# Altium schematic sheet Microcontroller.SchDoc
size A; SheetNumber: 3; SheetTotal: 5
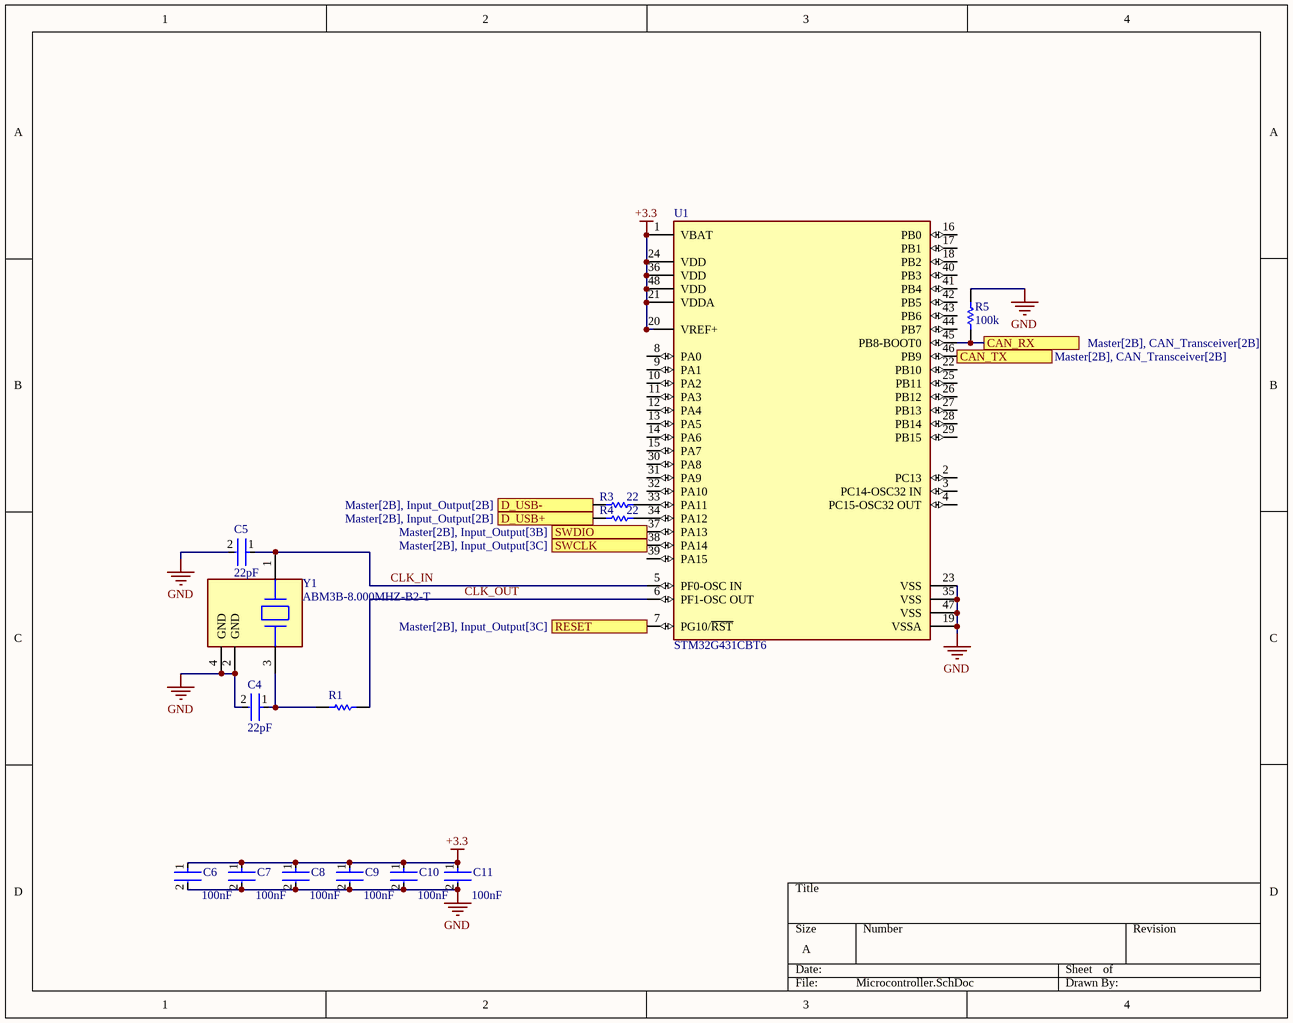
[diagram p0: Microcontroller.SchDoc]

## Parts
C4  22pF  [CAPC0603(1608)100_L]
C5  22pF  [CAPC0603(1608)100_L]
C6  100nF  [CAPC0603(1608)100_L]
C7  100nF  [CAPC0603(1608)100_L]
C8  100nF  [CAPC0603(1608)100_L]
C9  100nF  [CAPC0603(1608)100_L]
C10  100nF  [CAPC0603(1608)100_L]
C11  100nF  [CAPC0603(1608)100_L]
R1  RES 0805  [RESC2013X50X30ML20T20]  (value not drawn)
R3  22  [RESC2013X50X30ML20T20]
R4  22  [RESC2013X50X30ML20T20]
R5  100k  [RESC2013X50X30ML20T20]
U1  STM32G431CBT6  [FP-LQFP48-5B-MFG]
Y1  ABM3B-8.000MHZ-B2-T  [FP-ABM3B-MFG]

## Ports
CAN_RX (see Master[2B], CAN_Transceiver[2B]), CAN_TX (see Master[2B], CAN_Transceiver[2B]), D_USB+ (see Master[2B], Input_Output[2B]), D_USB- (see Master[2B], Input_Output[2B]), RESET (see Master[2B], Input_Output[3C]), SWCLK (see Master[2B], Input_Output[3C]), SWDIO (see Master[2B], Input_Output[3B])

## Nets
+3.3: C6.1 C7.1 C8.1 C9.1 C10.1 C11.1 U1.1(VBAT) U1.20(VREF+) U1.21(VDDA) U1.24(VDD) U1.36(VDD) U1.48(VDD)
GND: C4.2 C5.2 C6.2 C7.2 C8.2 C9.2 C10.2 C11.2 R5.2 U1.19(VSSA) U1.23(VSS) U1.35(VSS) U1.47(VSS) Y1.2(GND) Y1.4(GND)
CAN_RX: R5.1 U1.45(PB8-BOOT0) ; port CAN_RX
CAN_TX: U1.46(PB9) ; port CAN_TX
CLK_IN: C5.1 U1.5(PF0-OSC_IN) Y1.1
CLK_OUT: R1.2 U1.6(PF1-OSC_OUT)
D_USB+: R4.1 ; port D_USB+
D_USB-: R3.1 ; port D_USB-
RESET: U1.7(PG10/~{RST}) ; port RESET
SWCLK: U1.38(PA14) ; port SWCLK
SWDIO: U1.37(PA13) ; port SWDIO
NetC4_1: C4.1 R1.1 Y1.3
NetR3_2: R3.2 U1.33(PA11)
NetR4_2: R4.2 U1.34(PA12)

Not connected (* = marked no-connect by the designer): U1 2(PC13) 3(PC14-OSC32_IN) 4(PC15-OSC32_OUT) 8(PA0) 9(PA1) 10(PA2) 11(PA3) 12(PA4) 13(PA5) 14(PA6) 15(PA7) 16(PB0) 17(PB1) 18(PB2) 22(PB10) 25(PB11) 26(PB12) 27(PB13) 28(PB14) 29(PB15) 30(PA8) 31(PA9) 32(PA10) 39(PA15) 40(PB3) 41(PB4) 42(PB5) 43(PB6) 44(PB7)

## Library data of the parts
C4-C11 = CMP-001-00083-4: GENERIC CAPACITOR 0805 or 0603(1608)
R1 R3-R5 = CMP-009-00177-4: Surface Mount 0805 Resistor
U1 = CMP-12105-000030-1: MAINSTREAM ARM CORTEX-M4+ MCU 17; Manufacturer: STMicroelectronics; Number Of Adc Channels: 17; Number Of I/Os: 38; Standoff Height: 0.05mm; Number Of Usb Channels: 1; Data Bus Width: 32bits; Number Of I2C Channels: 3; Number Of Pwm Channels: 31; Frequency: 170MHz; Memory Type: FLASH; Number Of Timers/Counters: 14; Ram Size: 32KBytes; Max Junction Temp: +105°C; Memory Size: 128KBytes; Min Supply Voltage: 1.62V; Max Supply Voltage: 3.6V; Number Of Uart Channels: 4; Interface: I2C,SPI,UART,USART,CAN,USB,LIN,IrDA,I2S
Y1 = CMP-1688-00002-2: Crystal 8MHz ±20ppm 18pF SMD-4 5mm x 3.2mm; ESR (Equivalent Series Resistance): 200R; Frequency Stability: 50ppm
